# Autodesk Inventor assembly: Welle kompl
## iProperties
Created: 2006-11
Part Number: Welle kompl
Cost Center: 0,875 kg
Document SubType Name: Assembly
Designer: Schmidt
Authority: 111447 mm^3
Mass: 883.499 g
Surface Area: 372.26 cm^2
Volume: 112.477 cm^3
Density: 7.85493 g/cm^3
SaveDate: 2006-11-05
SaveTime: 22:51
TotalMass: 0,875 kg
TotalVolume: 111447 mm^3
Author: Schmidt
